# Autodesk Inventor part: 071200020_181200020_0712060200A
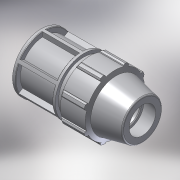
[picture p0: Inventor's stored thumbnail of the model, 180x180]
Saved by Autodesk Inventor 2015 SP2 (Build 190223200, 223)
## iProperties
Created: 2017-02
Part Number: 071200020_181200020_0712060200A
Material: PVC-Piping
Description: PLASSON END PLUG 20
Document SubType Name: Modeling
Designer: KIM
Mass: 92.6774 g
Surface Area: 199.44 cm^2
Volume: 66.1981 cm^3
Density: 1.4 g/cm^3
Appearance: Smooth - White
Author: Кирилл
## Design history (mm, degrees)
derived "07120.ipt"
feature "Solid1::07120.ipt"
tag "TaggingFeature1"
body "Solid1"
other parameters: "d4" = 11.28571, "d5" = 19.75, "d7" = 48, "d8" = 36, "d9" = 11.28571, "d11" = 2.25714, "d12" = 38.4, "d13" = 120 deg, "d15" = 12 deg, "d16" = 43.2, "d18" = 1, "d19" = 35 deg, "d20" = 17.5 deg, "d21" = 44.64, "d23" = 0, "d25" = 360 deg, "d27" = 0.96, "d34" = 2.4, "d36" = 0, "d42" = 19.75, "d43" = 1.44, "d46" = 0.6, "d53" = 0.4, "d55" = 360 deg, "d59" = 27.65, "d64" = 79, "d66" = 4.8, "d67" = 2.4, "d68" = 74, "E_" = 48, "H_" = 79, "l_" = 74
